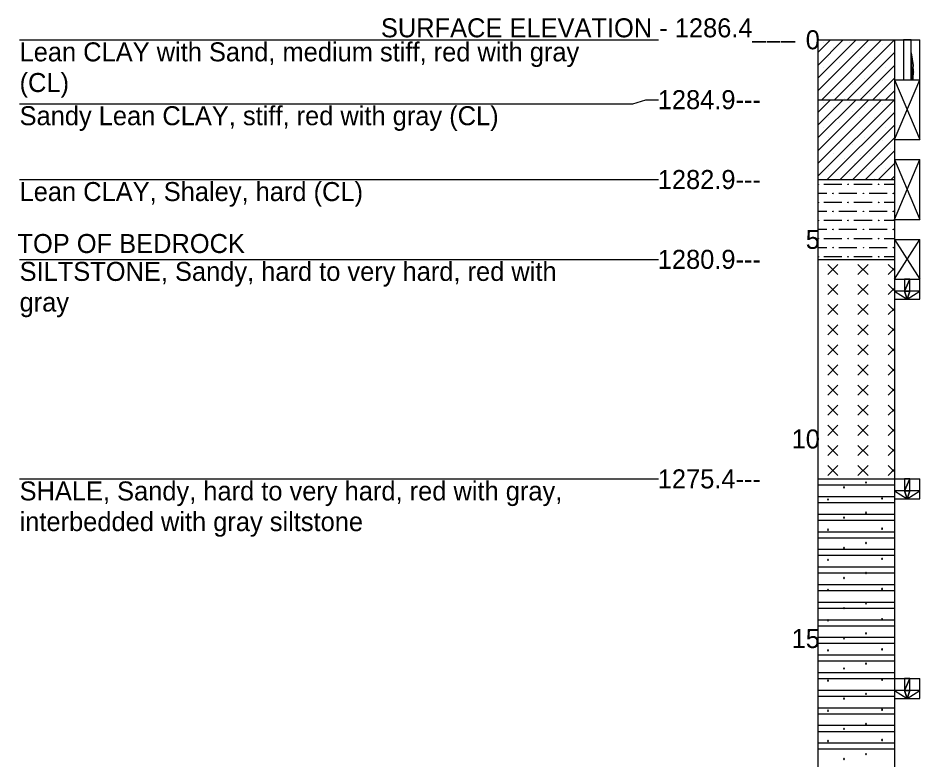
# Model space of a CAD drawing. Extents: x -2 to 138, y 24 to 58.
# Drawn here: x 27.87 to 33.76, y 44.24 to 49.08 of the extents above; entities that cross this region are included whole.
import ezdxf

# ---------------------------------------------------------------- set-up
doc = ezdxf.new("R2010")
doc.units = 0

# ---------------------------------------------------------------- blocks, each defined once
blk = doc.blocks.new('POINT_DISPLAY')
blk.add_line((0, 0), (0, 0))

msp = doc.modelspace()

# ---------------------------------------------------------------- linework, layer by layer
for points in [[(27.8838, 48.9382), (32.0505, 48.9382)], [(33.0889, 48.8549), (33.1722, 48.9382)], [(33.0889, 48.7715), (33.2556, 48.9382)], [(33.0889, 48.6882), (33.3389, 48.9382)], [(33.0889, 48.6049), (33.4222, 48.9382)], [(33.0889, 48.9382), (33.0889, 39.5632)], [(33.0889, 48.9382), (33.5889, 48.9382)], [(33.115, 48.5476), (33.5056, 48.9382)], [(33.1983, 48.5476), (33.5889, 48.9382)], [(33.5889, 48.9382), (33.7556, 48.9382)], [(33.5889, 48.9382), (33.5889, 39.5632)], [(33.7556, 48.6778), (33.7556, 48.9382)], [(33.2816, 48.5476), (33.5889, 48.8549)], [(33.365, 48.5476), (33.5889, 48.7715)], [(33.4483, 48.5476), (33.5889, 48.6882)], [(33.5889, 48.6778), (33.7556, 48.6778)], [(33.5889, 48.6778), (33.7556, 48.2872)], [(33.5889, 48.2872), (33.7556, 48.6778)], [(33.5889, 48.6778), (33.7556, 48.6778)], [(33.7556, 48.2872), (33.7556, 48.6778)], [(33.5316, 48.5476), (33.5889, 48.6049)], [(27.8838, 48.5215), (31.8838, 48.5215), (31.9671, 48.5476), (32.0505, 48.5476)], [(33.0889, 48.5476), (33.5889, 48.5476)], [(33.0889, 48.4642), (33.1722, 48.5476)], [(33.0889, 48.3809), (33.2556, 48.5476)], [(33.0889, 48.2976), (33.3389, 48.5476)], [(33.0889, 48.2142), (33.4222, 48.5476)], [(33.0889, 48.1309), (33.5056, 48.5476)], [(33.0889, 48.0476), (33.5889, 48.5476)], [(33.1514, 48.0267), (33.5889, 48.4642)], [(33.2347, 48.0267), (33.5889, 48.3809)], [(33.3181, 48.0267), (33.5889, 48.2976)], [(33.5889, 48.2872), (33.7556, 48.2872)], [(33.4014, 48.0267), (33.5889, 48.2142)], [(33.4847, 48.0267), (33.5889, 48.1309)], [(33.5889, 48.157), (33.7556, 47.7663)], [(33.5889, 47.7663), (33.7556, 48.157)], [(33.5889, 48.157), (33.7556, 48.157)], [(33.7556, 47.7663), (33.7556, 48.157)], [(27.8838, 48.0267), (32.0505, 48.0267)], [(33.0889, 48.0267), (33.5889, 48.0267)], [(33.0889, 47.9972), (33.0929, 47.9972), (33.0929, 47.9933), (33.0889, 47.9972)], [(33.1283, 47.9972), (33.2464, 47.9972)], [(33.2858, 47.9972), (33.2897, 47.9972), (33.2858, 47.9933), (33.2858, 47.9972)], [(33.3251, 47.9972), (33.4432, 47.9972)], [(33.4826, 47.9972), (33.4866, 47.9972), (33.4866, 47.9933), (33.4826, 47.9972)], [(33.522, 47.9972), (33.5889, 47.9972)], [(33.5681, 48.0267), (33.5889, 48.0476)], [(33.0889, 47.9382), (33.148, 47.9382)], [(33.1873, 47.9382), (33.1913, 47.9382), (33.1873, 47.9342), (33.1873, 47.9382)], [(33.2267, 47.9382), (33.3448, 47.9382)], [(33.3842, 47.9382), (33.3881, 47.9382), (33.3881, 47.9342), (33.3842, 47.9382)], [(33.4236, 47.9382), (33.4826, 47.9382)], [(33.4826, 47.9382), (33.5417, 47.9382)], [(33.581, 47.9382), (33.585, 47.9382), (33.581, 47.9342), (33.581, 47.9382)], [(33.0889, 47.8791), (33.0929, 47.8791), (33.0929, 47.8752), (33.0889, 47.8791)], [(33.1283, 47.8791), (33.2464, 47.8791)], [(33.2858, 47.8791), (33.2897, 47.8791), (33.2858, 47.8752), (33.2858, 47.8791)], [(33.3251, 47.8791), (33.4432, 47.8791)], [(33.4826, 47.8791), (33.4866, 47.8791), (33.4866, 47.8752), (33.4826, 47.8791)], [(33.522, 47.8791), (33.5889, 47.8791)], [(33.0889, 47.82), (33.148, 47.82)], [(33.1873, 47.82), (33.1913, 47.82), (33.1873, 47.8161), (33.1873, 47.82)], [(33.2267, 47.82), (33.3448, 47.82)], [(33.3842, 47.82), (33.3881, 47.82), (33.3881, 47.8161), (33.3842, 47.82)], [(33.4236, 47.82), (33.4826, 47.82)], [(33.4826, 47.82), (33.5417, 47.82)], [(33.581, 47.82), (33.585, 47.82), (33.581, 47.8161), (33.581, 47.82)], [(33.0889, 47.761), (33.0929, 47.761), (33.0929, 47.7571), (33.0889, 47.761)], [(33.1283, 47.761), (33.2464, 47.761)], [(33.2858, 47.761), (33.2897, 47.761), (33.2858, 47.7571), (33.2858, 47.761)], [(33.3251, 47.761), (33.4432, 47.761)], [(33.4826, 47.761), (33.4866, 47.761), (33.4866, 47.7571), (33.4826, 47.761)], [(33.522, 47.761), (33.5889, 47.761)], [(33.5889, 47.7663), (33.7556, 47.7663)], [(33.0889, 47.7019), (33.148, 47.7019)], [(33.1873, 47.7019), (33.1913, 47.7019), (33.1873, 47.698), (33.1873, 47.7019)], [(33.2267, 47.7019), (33.3448, 47.7019)], [(33.3842, 47.7019), (33.3881, 47.7019), (33.3881, 47.698), (33.3842, 47.7019)], [(33.4236, 47.7019), (33.4826, 47.7019)], [(33.4826, 47.7019), (33.5417, 47.7019)], [(33.581, 47.7019), (33.585, 47.7019), (33.581, 47.698), (33.581, 47.7019)], [(33.0889, 47.6429), (33.0929, 47.6429), (33.0929, 47.6389), (33.0889, 47.6429)], [(33.1283, 47.6429), (33.2464, 47.6429)], [(33.2858, 47.6429), (33.2897, 47.6429), (33.2858, 47.6389), (33.2858, 47.6429)], [(33.3251, 47.6429), (33.4432, 47.6429)], [(33.4826, 47.6429), (33.4866, 47.6429), (33.4866, 47.6389), (33.4826, 47.6429)], [(33.522, 47.6429), (33.5889, 47.6429)], [(33.5889, 47.6361), (33.7556, 47.3757)], [(33.5889, 47.3757), (33.7556, 47.6361)], [(33.5889, 47.6361), (33.7556, 47.6361)], [(33.7556, 47.3757), (33.7556, 47.6361)], [(33.0889, 47.5838), (33.148, 47.5838)], [(33.1873, 47.5838), (33.1913, 47.5838), (33.1873, 47.5799), (33.1873, 47.5838)], [(33.2267, 47.5838), (33.3448, 47.5838)], [(33.3842, 47.5838), (33.3881, 47.5838), (33.3881, 47.5799), (33.3842, 47.5838)], [(33.4236, 47.5838), (33.4826, 47.5838)], [(33.4826, 47.5838), (33.5417, 47.5838)], [(33.581, 47.5838), (33.585, 47.5838), (33.581, 47.5799), (33.581, 47.5838)], [(27.8838, 47.5059), (32.0505, 47.5059)], [(33.0889, 47.5248), (33.0929, 47.5248), (33.0929, 47.5208), (33.0889, 47.5248)], [(33.0889, 47.5059), (33.5889, 47.5059)], [(33.1283, 47.5248), (33.2464, 47.5248)], [(33.2201, 47.4731), (33.1545, 47.4075)], [(33.1545, 47.4731), (33.2201, 47.4075)], [(33.2858, 47.5248), (33.2897, 47.5248), (33.2858, 47.5208), (33.2858, 47.5248)], [(33.3251, 47.5248), (33.4432, 47.5248)], [(33.417, 47.4731), (33.3514, 47.4075)], [(33.3514, 47.4731), (33.417, 47.4075)], [(33.4826, 47.5248), (33.4866, 47.5248), (33.4866, 47.5208), (33.4826, 47.5248)], [(33.522, 47.5248), (33.5889, 47.5248)], [(33.5482, 47.4731), (33.5889, 47.4324)], [(33.5889, 47.4482), (33.5482, 47.4075)], [(33.5889, 47.3757), (33.7556, 47.3757)], [(33.5889, 47.3757), (33.7556, 47.3757)], [(33.7556, 47.2455), (33.7556, 47.3757)], [(33.2201, 47.3419), (33.1545, 47.2763)], [(33.1545, 47.3419), (33.2201, 47.2763)], [(33.417, 47.3419), (33.3514, 47.2763)], [(33.3514, 47.3419), (33.417, 47.2763)], [(33.5482, 47.3419), (33.5889, 47.3012)], [(33.5889, 47.3169), (33.5482, 47.2763)], [(33.5889, 47.2455), (33.7556, 47.2455)], [(33.2201, 47.2106), (33.1545, 47.145)], [(33.1545, 47.2106), (33.2201, 47.145)], [(33.417, 47.2106), (33.3514, 47.145)], [(33.3514, 47.2106), (33.417, 47.145)], [(33.5482, 47.2106), (33.5889, 47.17)], [(33.5889, 47.1857), (33.5482, 47.145)], [(33.2201, 47.0794), (33.1545, 47.0138)], [(33.1545, 47.0794), (33.2201, 47.0138)], [(33.417, 47.0794), (33.3514, 47.0138)], [(33.3514, 47.0794), (33.417, 47.0138)], [(33.5482, 47.0794), (33.5889, 47.0387)], [(33.5889, 47.0545), (33.5482, 47.0138)], [(33.2201, 46.9482), (33.1545, 46.8825)], [(33.1545, 46.9482), (33.2201, 46.8825)], [(33.417, 46.9482), (33.3514, 46.8825)], [(33.3514, 46.9482), (33.417, 46.8825)], [(33.5482, 46.9482), (33.5889, 46.9075)], [(33.5889, 46.9232), (33.5482, 46.8825)], [(33.2201, 46.8169), (33.1545, 46.7513)], [(33.1545, 46.8169), (33.2201, 46.7513)], [(33.417, 46.8169), (33.3514, 46.7513)], [(33.3514, 46.8169), (33.417, 46.7513)], [(33.5482, 46.8169), (33.5889, 46.7763)], [(33.5889, 46.792), (33.5482, 46.7513)], [(33.2201, 46.6857), (33.1545, 46.6201)], [(33.1545, 46.6857), (33.2201, 46.6201)], [(33.417, 46.6857), (33.3514, 46.6201)], [(33.3514, 46.6857), (33.417, 46.6201)], [(33.5482, 46.6857), (33.5889, 46.645)], [(33.5889, 46.6608), (33.5482, 46.6201)], [(33.2201, 46.5545), (33.1545, 46.4888)], [(33.1545, 46.5545), (33.2201, 46.4888)], [(33.417, 46.5545), (33.3514, 46.4888)], [(33.3514, 46.5545), (33.417, 46.4888)], [(33.5482, 46.5545), (33.5889, 46.5138)], [(33.5889, 46.5295), (33.5482, 46.4888)], [(33.2201, 46.4232), (33.1545, 46.3576)], [(33.1545, 46.4232), (33.2201, 46.3576)], [(33.417, 46.4232), (33.3514, 46.3576)], [(33.3514, 46.4232), (33.417, 46.3576)], [(33.5482, 46.4232), (33.5889, 46.3825)], [(33.5889, 46.3983), (33.5482, 46.3576)], [(33.2201, 46.292), (33.1545, 46.2264)], [(33.1545, 46.292), (33.2201, 46.2264)], [(33.417, 46.292), (33.3514, 46.2264)], [(33.3514, 46.292), (33.417, 46.2264)], [(33.5482, 46.292), (33.5889, 46.2513)], [(33.5889, 46.2671), (33.5482, 46.2264)], [(33.2201, 46.1608), (33.1545, 46.0951)], [(33.1545, 46.1608), (33.2201, 46.0951)], [(33.417, 46.1608), (33.3514, 46.0951)], [(33.3514, 46.1608), (33.417, 46.0951)], [(33.5482, 46.1608), (33.564, 46.145), (33.5889, 46.1201)], [(33.5889, 46.1358), (33.5728, 46.1197), (33.5482, 46.0951)], [(27.8838, 46.0736), (32.0505, 46.0736)], [(33.0889, 46.0736), (33.5889, 46.0736)], [(33.0889, 46.0736), (33.5889, 46.0736)], [(33.5889, 46.0736), (33.7556, 46.0736)], [(33.7556, 45.9434), (33.7556, 46.0736)], [(33.0889, 46.0342), (33.5889, 46.0342)], [(33.264, 46.0178), (33.2623, 46.0207), (33.2591, 46.0207), (33.2574, 46.0178), (33.2591, 46.015), (33.2623, 46.015), (33.264, 46.0178)], [(33.4066, 46.0497), (33.4049, 46.0525), (33.4016, 46.0525), (33.4, 46.0497), (33.4016, 46.0468), (33.4049, 46.0468), (33.4066, 46.0497)], [(33.0889, 45.9588), (33.5889, 45.9588)], [(33.1593, 45.9388), (33.1577, 45.9417), (33.1544, 45.9417), (33.1528, 45.9388), (33.1544, 45.936), (33.1577, 45.936), (33.1593, 45.9388)], [(33.5121, 45.9453), (33.5104, 45.9482), (33.5072, 45.9482), (33.5055, 45.9453), (33.5072, 45.9425), (33.5104, 45.9425), (33.5121, 45.9453)], [(33.5889, 45.9434), (33.7556, 45.9434)], [(33.0889, 45.9194), (33.5889, 45.9194)], [(33.0889, 45.844), (33.5889, 45.844)], [(33.264, 45.8209), (33.2623, 45.8238), (33.2591, 45.8238), (33.2574, 45.821), (33.2591, 45.8181), (33.2623, 45.8181), (33.264, 45.8209)], [(33.4066, 45.8528), (33.4049, 45.8556), (33.4016, 45.8556), (33.4, 45.8528), (33.4016, 45.85), (33.4049, 45.85), (33.4066, 45.8528)], [(33.0889, 45.8046), (33.5889, 45.8046)], [(33.0889, 45.7291), (33.5889, 45.7291)], [(33.1593, 45.742), (33.1577, 45.7448), (33.1544, 45.7448), (33.1528, 45.742), (33.1544, 45.7391), (33.1577, 45.7391), (33.1593, 45.742)], [(33.5121, 45.7485), (33.5104, 45.7514), (33.5072, 45.7514), (33.5055, 45.7485), (33.5072, 45.7457), (33.5104, 45.7457), (33.5121, 45.7485)], [(33.0889, 45.6898), (33.5889, 45.6898)], [(33.4066, 45.656), (33.4049, 45.6588), (33.4016, 45.6588), (33.4, 45.656), (33.4016, 45.6531), (33.4049, 45.6531), (33.4066, 45.656)], [(33.0889, 45.6143), (33.5889, 45.6143)], [(33.264, 45.6241), (33.2623, 45.627), (33.2591, 45.627), (33.2574, 45.6241), (33.2591, 45.6213), (33.2623, 45.6213), (33.264, 45.6241)], [(33.0889, 45.5749), (33.5889, 45.5749)], [(33.1593, 45.5451), (33.1577, 45.548), (33.1544, 45.548), (33.1528, 45.5451), (33.1544, 45.5423), (33.1577, 45.5423), (33.1593, 45.5451)], [(33.5121, 45.5516), (33.5104, 45.5545), (33.5072, 45.5545), (33.5055, 45.5516), (33.5072, 45.5488), (33.5104, 45.5488), (33.5121, 45.5516)], [(33.0889, 45.4995), (33.5889, 45.4995)], [(33.0889, 45.4601), (33.5889, 45.4601)], [(33.264, 45.4272), (33.2623, 45.4301), (33.2591, 45.4301), (33.2574, 45.4273), (33.2591, 45.4244), (33.2623, 45.4244), (33.264, 45.4272)], [(33.4066, 45.4591), (33.4049, 45.4619), (33.4016, 45.4619), (33.4, 45.4591), (33.4016, 45.4563), (33.4049, 45.4563), (33.4066, 45.4591)], [(33.0889, 45.3846), (33.5889, 45.3846)], [(33.1593, 45.3483), (33.1577, 45.3511), (33.1544, 45.3511), (33.1528, 45.3483), (33.1544, 45.3454), (33.1577, 45.3454), (33.1593, 45.3483)], [(33.5121, 45.3548), (33.5104, 45.3577), (33.5072, 45.3577), (33.5055, 45.3548), (33.5072, 45.352), (33.5104, 45.352), (33.5121, 45.3548)], [(33.0889, 45.3453), (33.5889, 45.3453)], [(33.0889, 45.2698), (33.5889, 45.2698)], [(33.264, 45.2304), (33.2623, 45.2333), (33.2591, 45.2333), (33.2574, 45.2304), (33.2591, 45.2276), (33.2623, 45.2276), (33.264, 45.2304)], [(33.4066, 45.2623), (33.4049, 45.2651), (33.4016, 45.2651), (33.4, 45.2623), (33.4016, 45.2594), (33.4049, 45.2594), (33.4066, 45.2623)], [(33.0889, 45.2304), (33.5889, 45.2304)], [(33.0889, 45.155), (33.5889, 45.155)], [(33.0889, 45.1156), (33.5889, 45.1156)], [(33.1593, 45.1514), (33.1577, 45.1543), (33.1544, 45.1543), (33.1528, 45.1514), (33.1544, 45.1486), (33.1577, 45.1486), (33.1593, 45.1514)], [(33.5121, 45.1579), (33.5104, 45.1608), (33.5072, 45.1608), (33.5055, 45.1579), (33.5072, 45.1551), (33.5104, 45.1551), (33.5121, 45.1579)], [(33.4066, 45.0654), (33.4049, 45.0682), (33.4016, 45.0682), (33.4, 45.0654), (33.4016, 45.0626), (33.4049, 45.0626), (33.4066, 45.0654)], [(33.0889, 45.0402), (33.5889, 45.0402)], [(33.0889, 45.0008), (33.5889, 45.0008)], [(33.264, 45.0335), (33.2623, 45.0364), (33.2591, 45.0364), (33.2574, 45.0336), (33.2591, 45.0307), (33.2623, 45.0307), (33.264, 45.0335)], [(33.1593, 44.9546), (33.1577, 44.9574), (33.1544, 44.9574), (33.1528, 44.9546), (33.1544, 44.9517), (33.1577, 44.9517), (33.1593, 44.9546)], [(33.5121, 44.9611), (33.5104, 44.964), (33.5072, 44.964), (33.5055, 44.9611), (33.5072, 44.9583), (33.5104, 44.9583), (33.5121, 44.9611)], [(33.0889, 44.9253), (33.5889, 44.9253)], [(33.0889, 44.886), (33.5889, 44.886)], [(33.264, 44.8367), (33.2623, 44.8396), (33.2591, 44.8396), (33.2574, 44.8367), (33.2591, 44.8339), (33.2623, 44.8339), (33.264, 44.8367)], [(33.4066, 44.8686), (33.4049, 44.8714), (33.4016, 44.8714), (33.4, 44.8686), (33.4016, 44.8657), (33.4049, 44.8657), (33.4066, 44.8686)], [(33.0889, 44.8105), (33.5889, 44.8105)], [(33.0889, 44.7711), (33.5889, 44.7711)], [(33.5121, 44.7642), (33.5104, 44.7671), (33.5072, 44.7671), (33.5055, 44.7642), (33.5072, 44.7614), (33.5104, 44.7614), (33.5121, 44.7642)], [(33.5889, 44.7715), (33.7556, 44.7715)], [(33.7556, 44.6413), (33.7556, 44.7715)], [(33.1593, 44.7577), (33.1577, 44.7606), (33.1544, 44.7606), (33.1528, 44.7577), (33.1544, 44.7549), (33.1577, 44.7549), (33.1593, 44.7577)], [(33.0889, 44.6957), (33.5889, 44.6957)], [(33.0889, 44.6563), (33.5889, 44.6563)], [(33.4066, 44.6717), (33.4049, 44.6745), (33.4016, 44.6745), (33.4, 44.6717), (33.4016, 44.6689), (33.4049, 44.6689), (33.4066, 44.6717)], [(33.264, 44.6398), (33.2623, 44.6427), (33.2591, 44.6427), (33.2574, 44.6399), (33.2591, 44.637), (33.2623, 44.637), (33.264, 44.6398)], [(33.5889, 44.6413), (33.7556, 44.6413)], [(33.0889, 44.5808), (33.5889, 44.5808)], [(33.0889, 44.5415), (33.5889, 44.5415)], [(33.1593, 44.5609), (33.1577, 44.5637), (33.1544, 44.5637), (33.1528, 44.5609), (33.1544, 44.558), (33.1577, 44.558), (33.1593, 44.5609)], [(33.5121, 44.5674), (33.5104, 44.5703), (33.5072, 44.5703), (33.5055, 44.5674), (33.5072, 44.5646), (33.5104, 44.5646), (33.5121, 44.5674)], [(33.4066, 44.4749), (33.4049, 44.4777), (33.4016, 44.4777), (33.4, 44.4749), (33.4016, 44.472), (33.4049, 44.472), (33.4066, 44.4749)], [(33.0889, 44.466), (33.5889, 44.466)], [(33.0889, 44.4266), (33.5889, 44.4266)], [(33.264, 44.443), (33.2623, 44.4459), (33.2591, 44.4459), (33.2574, 44.443), (33.2591, 44.4402), (33.2623, 44.4402), (33.264, 44.443)], [(33.0889, 44.3512), (33.5889, 44.3512)], [(33.1593, 44.364), (33.1577, 44.3669), (33.1544, 44.3669), (33.1528, 44.364), (33.1544, 44.3612), (33.1577, 44.3612), (33.1593, 44.364)], [(33.5121, 44.3705), (33.5104, 44.3734), (33.5072, 44.3734), (33.5055, 44.3705), (33.5072, 44.3677), (33.5104, 44.3677), (33.5121, 44.3705)], [(33.0889, 44.3118), (33.5889, 44.3118)], [(33.264, 44.2461), (33.2623, 44.249), (33.2591, 44.249), (33.2574, 44.2462), (33.2591, 44.2433), (33.2623, 44.2433), (33.264, 44.2461)], [(33.4066, 44.278), (33.4049, 44.2808), (33.4016, 44.2808), (33.4, 44.278), (33.4016, 44.2752), (33.4049, 44.2752), (33.4066, 44.278)]]:
    msp.add_lwpolyline(points)
for points in [[(33.6472, 48.9382), (33.6472, 48.6778), (33.6972, 48.6778), (33.6972, 48.9382)], [(33.7119, 48.7715), (33.7059, 48.8132), (33.6972, 48.8532), (33.7119, 48.7715)], [(33.6972, 48.8532), (33.6972, 48.6778), (33.7119, 48.7715), (33.6972, 48.8532)], [(33.6972, 48.6778), (33.7139, 48.7299), (33.7119, 48.7715), (33.6972, 48.6778)], [(33.6972, 48.6778), (33.7119, 48.6882), (33.7139, 48.7299), (33.6972, 48.6778)], [(33.6972, 48.6778), (33.7104, 48.6778), (33.7119, 48.6882), (33.6972, 48.6778)], [(33.6556, 47.2976), (33.6889, 47.2976), (33.6889, 47.3757), (33.6556, 47.2976)], [(33.6556, 47.2976), (33.6889, 47.3757), (33.6556, 47.3757), (33.6556, 47.2976)], [(33.6556, 47.2976), (33.5889, 47.2976), (33.6722, 47.2455), (33.6556, 47.2976)], [(33.6556, 47.2976), (33.6722, 47.2455), (33.6889, 47.2976), (33.6556, 47.2976)], [(33.6722, 47.2455), (33.7556, 47.2976), (33.6889, 47.2976), (33.6722, 47.2455)], [(33.6556, 45.9955), (33.6889, 45.9955), (33.6889, 46.0736), (33.6556, 45.9955)], [(33.6556, 45.9955), (33.6889, 46.0736), (33.6556, 46.0736), (33.6556, 45.9955)], [(33.6556, 45.9955), (33.5889, 45.9955), (33.6722, 45.9434), (33.6556, 45.9955)], [(33.6556, 45.9955), (33.6722, 45.9434), (33.6889, 45.9955), (33.6556, 45.9955)], [(33.6722, 45.9434), (33.7556, 45.9955), (33.6889, 45.9955), (33.6722, 45.9434)], [(33.6556, 44.6934), (33.6889, 44.6934), (33.6889, 44.7715), (33.6556, 44.6934)], [(33.6556, 44.6934), (33.6889, 44.7715), (33.6556, 44.7715), (33.6556, 44.6934)], [(33.6556, 44.6934), (33.5889, 44.6934), (33.6722, 44.6413), (33.6556, 44.6934)], [(33.6556, 44.6934), (33.6722, 44.6413), (33.6889, 44.6934), (33.6556, 44.6934)], [(33.6722, 44.6413), (33.7556, 44.6934), (33.6889, 44.6934), (33.6722, 44.6413)]]:
    msp.add_lwpolyline(points, close=True)

# ---------------------------------------------------------------- block references
at = {"xscale": 0.01, "yscale": 0.01}
for p in [(33.1281, 48.9215), (33.1947, 48.8882), (33.2947, 48.9215), (33.3947, 48.8882), (33.5144, 48.9049), (33.0947, 48.8549), (33.1614, 48.8215), (33.3177, 48.8579), (33.3614, 48.8215), (33.4614, 48.8215), (33.5614, 48.8549), (33.2281, 48.7882), (33.1281, 48.7549), (33.2947, 48.7215), (33.3782, 48.7458), (33.5281, 48.7549), (33.1614, 48.6882), (33.2281, 48.6549), (33.3131, 48.6443), (33.3947, 48.6882), (33.5129, 48.67), (33.0947, 48.6215), (33.1947, 48.5882), (33.4281, 48.5882), (33.5614, 48.6215), (33.1281, 48.5309), (33.2614, 48.5549), (33.2947, 48.5309), (33.3646, 48.5746), (33.4947, 48.5549), (33.1947, 48.4976), (33.3177, 48.4673), (33.3947, 48.4976), (33.5144, 48.5142), (33.0947, 48.4642), (33.1614, 48.4309), (33.3614, 48.4309), (33.4614, 48.4309), (33.5614, 48.4642), (33.1281, 48.3642), (33.2281, 48.3976), (33.3782, 48.3552), (33.5281, 48.3642), (33.1614, 48.2976), (33.2947, 48.3309), (33.3947, 48.2976), (33.2281, 48.2642), (33.3131, 48.2536), (33.5129, 48.2794), (33.0947, 48.2309), (33.1947, 48.1976), (33.3646, 48.1839), (33.4281, 48.1976), (33.5614, 48.2309), (33.2614, 48.1642), (33.3281, 48.1309), (33.4947, 48.1642), (33.1614, 48.0976), (33.2947, 48.0642), (33.407, 48.0976), (33.5281, 48.0976), (33.0947, 48.0309), (33.4614, 48.0309)]:
    msp.add_blockref('POINT_DISPLAY', p, dxfattribs=at)

# ---------------------------------------------------------------- texts
for s, p in [('SURFACE ELEVATION - 1286.4___', (30.2401, 48.9544)), ('0', (33.0106, 48.8762)), ('Lean CLAY with Sand, medium stiff, red with gray', (27.8838, 48.7975)), ('(CL)', (27.8838, 48.5975)), ('1284.9---', (32.0456, 48.4856)), ('Sandy Lean CLAY, stiff, red with gray (CL)', (27.8838, 48.3809)), ('1282.9---', (32.0456, 47.9647)), ('Lean CLAY, Shaley, hard (CL)', (27.8838, 47.8861)), ('TOP OF BEDROCK', (27.87, 47.5472)), ('5', (33.0106, 47.5741)), ('1280.9---', (32.0456, 47.4439)), ('SILTSTONE, Sandy, hard to very hard, red with', (27.8838, 47.3652)), ('gray', (27.8838, 47.1652)), ('10', (32.9185, 46.272)), ('1275.4---', (32.0456, 46.0116)), ('SHALE, Sandy, hard to very hard, red with gray,', (27.8838, 45.933)), ('interbedded with gray siltstone', (27.8838, 45.733)), ('15', (32.9185, 44.97))]:
    msp.add_text(s, height=0.124).set_placement(p)

doc.saveas('drawing.dxf')
